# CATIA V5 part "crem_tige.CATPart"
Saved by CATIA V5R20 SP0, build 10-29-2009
Part number: crem_tige
Definition: NONE
Nomenclature: 1
Source: Unknown
Description: PART-1-DESC
Bounding box of the stored display mesh (mm): x -30 to 0, y -2.5 to 6, z -8 to 2
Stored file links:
  F:\Catia_finish\crem_tige.CATPart
  D:\Ecole\Ifma\2A\S3\CFAO\ThinkMotion\Catia\crem_copie_1.CATPart
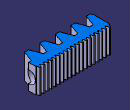
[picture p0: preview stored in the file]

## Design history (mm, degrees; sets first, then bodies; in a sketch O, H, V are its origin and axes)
Sketch1 on face of Solid2, origin (0, 17.5, 8), H (-1, 0, 0), V (0, -1, 0)
  line L1 (-14, -3.4) -> (39, -3.4)
  line L2 (39, -3.4) -> (39, 13.6)
  line L3 (39, 13.6) -> (-14, 13.6)
  line L4 (-14, 13.6) -> (-14, -3.4)
  reference projected line E1 (0, 0) -> (1005, 0) from edge [face of Solid2 | face of Solid2]
  distance L3 E1 = 13.6
  horizontal: L1 H, L3 H
  vertical: L2 V, L4 V
Pocket1: profile Sketch1, direction (0, 0, -1), through (limit type 3)
Sketch2 on face of Pad1, origin (0, 0, 2), H (1, 0, 0), V (0, 1, 0)
  line L1 (29, -14.1) -> (-37, -14.1)
  line L2 (-37, -14.1) -> (-37, 3.9)
  line L3 (-37, 3.9) -> (29, 3.9)
  line L4 (29, 3.9) -> (29, -14.1)
  reference projected point E1 (2.9342, 4.9) from vertex [face of Solid1 | face of Solid1 | face of Solid1]
  distance L3 E1 = 1
  horizontal: L1 H, L3 H
  vertical: L2 V, L4 V
Pocket2: profile Sketch2, direction (0, 0, -1), through (limit type 3)
Solid1: solid without history
Sketch3 on face of Solid2, origin (0, 0, -8), H (1, 0, 0), V (0, -1, 0)
  line L1 (-958, 170) -> (-30, 170)
  line L2 (-30, 170) -> (-30, -256)
  line L3 (-30, -256) -> (-958, -256)
  line L4 (-958, -256) -> (-958, 170)
  reference projected line E1 (0, -1.9) -> (0, -17.5) from edge [face of Solid2 | face of Solid2]
  distance E1 L2 = 30
  horizontal: L1 H, L3 H
  vertical: L2 V, L4 V
Pocket3: profile Sketch3, direction (0, 0, 1), through (limit type 3)
Set1
  Sketch4 on xy-plane, origin (0, 0, 0), H (1, 0, 0), V (0, 1, 0)
    line L1 (45, 40) -> (298, 40)
    line L2 (298, 40) -> (298, -31)
    line L3 (298, -31) -> (45, -31)
    line L4 (45, -31) -> (45, 40)
    distance L4 V = 45
    horizontal: L1 H, L3 H
    vertical: L2 V, L4 V
Body1 "1" (main body)
  Pocket4: profile Sketch4, direction (0, 0, -1), length 20, opposite side length 20
  Pad1: profile face of Solid1, direction along edge [face of Pocket4 from Sketch4.L4 | face of Solid1], length 2.5
  Body2
    Solid2 "1": solid without history
    Sketch5 on face of Pocket1 from Sketch1.L3, origin (0, 3.9, 0), H (-1, 0, 0), V (0, 0, 1)
      line L1 (-5, 16) -> (38, 16)
      line L2 (38, 16) -> (38, 2)
      line L3 (38, 2) -> (-5, 2)
      line L4 (-5, 2) -> (-5, 16)
      reference projected line E1 (0, -8) -> (30, -8) from edge [face of Solid2 | face of Pocket1 from Sketch1.L3]
      distance L3 E1 = 10
      horizontal: L1 H, L3 H
      vertical: L2 V, L4 V
    Pocket5: profile Sketch5, direction (0, 1, 0), through (limit type 3)
    Pocket6: profile face of Pocket2 from Sketch2.L3, length 0.1, deactivated
    Pad2: profile face of Pad1, direction along edge [face of Pocket3 from Sketch3.L2 | face of Pocket1 from Sketch1.L3], length 0, opposite side length 6
    Sketch6 on face of Pad2, origin (0, 0, -8), H (1, 0, 0), V (0, -1, 0)
      line L1 (48, -19) -> (0, -19)
      line L2 (0, -19) -> (0, 12)
      line L3 (0, 12) -> (48, 12)
      line L4 (48, 12) -> (48, -19)
      horizontal: L1 H, L3 H
      vertical: L2 V, L4 V
      coincidence: L2 V
    Pocket7: profile Sketch6, direction (0, 0, 1), through (limit type 3), opposite side through (limit type 3)
  Assemble1: tool Body2
  Sketch7 on face of Pad2, origin (0, 0, -8), H (1, 0, 0), V (0, -1, 0)
    line L1 (70, -21) -> (0, -21)
    line L2 (0, -21) -> (0, 20)
    line L3 (0, 20) -> (70, 20)
    line L4 (70, 20) -> (70, -21)
    horizontal: L1 H, L3 H
    vertical: L2 V, L4 V
    coincidence: L2 V
  Pocket8: profile Sketch7, direction (0, 0, 1), through (limit type 3)
  Sketch8 on face of Pad1, origin (-30, 0, 0), H (0, -1, 0), V (0, 0, 1)
    circle A1 centre (-2.2, -3) radius 2.5
    point P1 (-2.2, -3)
    reference projected line E1 (0, 2) -> (-4.9, 2) from edge [face of Pad1 | face of Pad1]
    reference projected line E2 (-1.9, 8) -> (-1.9, -8) from edge [face of Solid2 | face of Solid2]
    distance P1 E1 = 5
    radius A1 = 2.5
    distance P1 E2 = 0.3
  Pocket9: profile Sketch8, direction (1, 0, 0), through (limit type 3)
  Sketch9 on face of Solid2, origin (0, 0, -8), H (1, 0, 0), V (0, -1, 0)
    line L1 (-278, -280) -> (-4577, -280)
    line L2 (-4577, -280) -> (-4577, 877)
    line L3 (-4577, 877) -> (-278, 877)
    line L4 (-278, 877) -> (-278, -280)
    horizontal: L1 H, L3 H
    vertical: L2 V, L4 V
  Pocket10: profile Sketch9, direction (0, 0, 1), through (limit type 3)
